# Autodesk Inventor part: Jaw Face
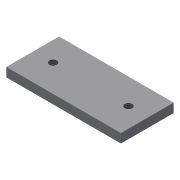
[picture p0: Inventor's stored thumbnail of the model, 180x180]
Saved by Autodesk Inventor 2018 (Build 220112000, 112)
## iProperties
Shininess: 77.0
Length Units: 11269
Angle Units: 11279
Time Units: 11290
Mass Units: 11283
Length Display Precision: 3
Angle Display Precision: 2
Compacted: True
Created: 2002-02
Part Number: Jaw Face
Document SubType Name: Modeling
Designer: ***
Density: 1 g/cm^3
Material: Generic
Mass: 15.6207 g
Surface Area: 67.651 cm^2
Volume: 15.6207 cm^3
Appearance: Default
Density: 0.0
Volumn: 0.0
Area: 0.0
PropertySet Name: Model Information
Control State: 0
Master: False
Checked Out: False
Author: ***
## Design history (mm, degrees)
sketch "Sketch1"
  geometry: L1 (-79.661, -8.43)-(-3.661, -8.43); L2 (-3.661, -8.43)-(-3.661, -43.43); L3 (-3.661, -43.43)-(-79.661, -43.43); L4 (-79.661, -43.43)-(-79.661, -8.43)
  constraints: 8 end point, 2 parallel, 1 horizontal, 1 perpendicular
  dimensions: "d0" = 76 distance of L2.end L3.end; "d3" = 35 distance of L1.end L2.end
extrude "Extrusion1" new body sketch "Sketch1" stored distance "d7" = 6; taper "d8" = 0 deg
hole "Hole1" diameter "d11" = 4.917; stored, may be unused: countersink angle "d15" = 90 deg, drill point angle "d17" = 118 deg; dims "d9" = 13, "d10" = 18, "d12" = 12, "d13" = 4, "d14" = 2, "d16" = 17.1
pattern_linear "Rectangular Pattern1" dims "d20" = -50
body "Solid1"
